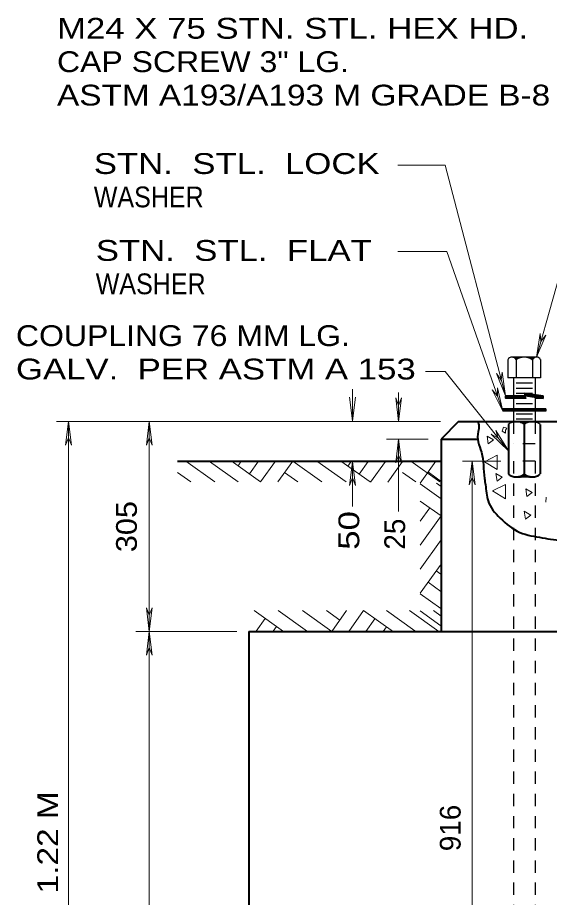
# Model space of a CAD drawing. Extents: x 312583 to 312854, y 144419 to 144597.
# Drawn here: x 312623.61 to 312643.06, y 144483.85 to 144515.99 of the extents above; entities that cross this region are included whole.
import ezdxf

# ---------------------------------------------------------------- set-up
doc = ezdxf.new("R2010")
doc.units = 0
doc.header["$LTSCALE"] = 0.3
doc.linetypes.add('SHORT_DASHED', pattern=[2.7, 1.5, -1.2])
for name, color, linetype, lineweight in [('1', 7, 'Continuous', 25), ('2', 7, 'Continuous', 13), ('52', 7, 'Continuous', 13)]:
    doc.layers.add(name, color=color, linetype=linetype, lineweight=lineweight)

msp = doc.modelspace()

# ---------------------------------------------------------------- linework, layer by layer
at = {"layer": '1'}
for p, q in [((312641.5397, 144503.4947), (312641.5397, 144502.8277)), ((312642.59, 144503.5867), (312641.693, 144503.5867)), ((312641.8387, 144503.4947), (312641.8387, 144502.8277)), ((312642.4367, 144503.4947), (312642.4367, 144502.8277)), ((312642.7357, 144503.4947), (312642.7357, 144502.8277)), ((312642.7357, 144502.8277), (312641.5397, 144502.8277)), ((312641.739, 144502.8277), (312641.739, 144501.233)), ((312641.8387, 144502.6437), (312642.4367, 144502.6437)), ((312642.5363, 144502.8277), (312642.5363, 144501.233)), ((312641.8387, 144502.452), (312642.4367, 144502.452)), ((312642.1683, 144502.176), (312641.4477, 144502.176)), ((312641.4477, 144502.1683), (312641.4477, 144502.0763)), ((312642.199, 144502.0763), (312641.4477, 144502.0763)), ((312641.8387, 144502.268), (312642.4367, 144502.268)), ((312642.8277, 144502.176), (312642.8277, 144502.0763)), ((312642.9273, 144501.7007), (312641.348, 144501.7007)), ((312641.348, 144501.7007), (312641.348, 144501.6087)), ((312642.9273, 144501.6777), (312641.348, 144501.6777)), ((312641.8387, 144501.8923), (312642.4367, 144501.8923)), ((312642.9273, 144501.7007), (312642.9273, 144501.6087)), ((312642.9273, 144501.6547), (312641.348, 144501.6547)), ((312642.9273, 144501.624), (312641.348, 144501.624)), ((312642.9273, 144501.6087), (312641.348, 144501.6087)), ((312641.8387, 144501.509), (312642.4367, 144501.509)), ((312642.5363, 144501.233), (312641.739, 144501.233)), ((312641.8387, 144501.325), (312642.4367, 144501.325)), ((312642.429, 144501.233), (312641.8463, 144501.233))]:
    msp.add_line(p, q, dxfattribs=at)
at = {"layer": '1', "lineweight": 40}
for p, q in [((312639.738, 144501.233), (312639.094, 144500.589)), ((312639.738, 144501.233), (312651.238, 144501.233)), ((312641.555, 144501.1257), (312641.555, 144499.3163)), ((312642.1377, 144501.233), (312642.1377, 144499.209)), ((312642.7203, 144501.1257), (312642.7203, 144499.3163)), ((312639.094, 144500.589), (312639.094, 144493.5663)), ((312639.094, 144500.589), (312640.428, 144500.589)), ((312629.4647, 144499.784), (312639.094, 144499.784)), ((312632.0713, 144493.5663), (312632.0713, 144470.5663)), ((312632.0713, 144493.5663), (312658.9047, 144493.5663))]:
    msp.add_line(p, q, dxfattribs=at)
at = {"layer": '1', "linetype": 'SHORT_DASHED'}
for p, q in [((312641.739, 144501.233), (312641.739, 144500.4203)), ((312642.5363, 144501.233), (312642.5363, 144500.4203)), ((312642.5363, 144500.4203), (312641.739, 144500.4203)), ((312642.5363, 144499.784), (312641.739, 144499.784)), ((312641.739, 144499.784), (312641.739, 144477.6273)), ((312642.5363, 144499.784), (312642.5363, 144477.6273)), ((312642.429, 144499.209), (312641.8463, 144499.209))]:
    msp.add_line(p, q, dxfattribs=at)
at = {"layer": '1'}
for points in [[(312641.7237, 144503.5867), (312642.061, 144503.579), (312642.0073, 144503.5713), (312641.969, 144503.5637), (312641.9077, 144503.5407), (312641.8387, 144503.4947), (312641.8157, 144503.533), (312641.7927, 144503.556), (312641.739, 144503.579), (312642.038, 144503.579), (312641.9537, 144503.5637), (312641.8923, 144503.533), (312641.8463, 144503.5023), (312641.7927, 144503.5483), (312641.762, 144503.5713), (312641.9997, 144503.579), (312641.9153, 144503.5483), (312641.8463, 144503.51), (312641.7773, 144503.5713), (312641.969, 144503.5713), (312641.8387, 144503.5177), (312641.7927, 144503.5637), (312641.9537, 144503.5713), (312641.8387, 144503.5253), (312641.8003, 144503.5637), (312641.923, 144503.5637), (312641.8387, 144503.5407), (312641.8157, 144503.556), (312641.8923, 144503.5637), (312641.8463, 144503.5407), (312641.831, 144503.556), (312641.8693, 144503.556), (312641.8463, 144503.5483)], [(312642.5517, 144503.5867), (312642.2143, 144503.579), (312642.268, 144503.5713), (312642.3063, 144503.5637), (312642.3753, 144503.5407), (312642.4367, 144503.4947), (312642.4597, 144503.533), (312642.4827, 144503.556), (312642.5363, 144503.579), (312642.245, 144503.579), (312642.3217, 144503.5637), (312642.383, 144503.533), (312642.429, 144503.5023), (312642.4827, 144503.5483), (312642.5133, 144503.5713), (312642.2757, 144503.579), (312642.36, 144503.5483), (312642.429, 144503.51), (312642.498, 144503.5713), (312642.3063, 144503.5713), (312642.4367, 144503.5177), (312642.4903, 144503.5637), (312642.3293, 144503.5713), (312642.4367, 144503.5253), (312642.475, 144503.5637), (312642.3523, 144503.5637), (312642.4367, 144503.5407), (312642.4597, 144503.556), (312642.383, 144503.5637), (312642.429, 144503.5407), (312642.4443, 144503.556), (312642.4137, 144503.556), (312642.429, 144503.5483)], [(312642.1837, 144502.0917), (312641.4553, 144502.0917), (312641.4553, 144502.1607), (312642.153, 144502.1607), (312642.176, 144502.0993), (312641.4707, 144502.0993), (312641.4707, 144502.1453), (312642.1453, 144502.1453), (312642.1607, 144502.107), (312641.486, 144502.1147), (312641.4937, 144502.13), (312641.4937, 144502.1377), (312642.1453, 144502.1377), (312642.153, 144502.1223), (312641.5013, 144502.1223)], [(312642.8277, 144502.176), (312642.1377, 144502.268), (312642.199, 144502.0763)], [(312642.5363, 144502.0763), (312642.8277, 144502.0917), (312642.82, 144502.1607), (312642.153, 144502.2527), (312642.1837, 144502.1837), (312642.544, 144502.13), (312642.5517, 144502.0917), (312642.8123, 144502.0993), (312642.8123, 144502.153), (312642.1683, 144502.2373), (312642.1913, 144502.1913), (312642.5593, 144502.13), (312642.567, 144502.0993), (312642.8047, 144502.107), (312642.8047, 144502.1377), (312642.199, 144502.222), (312642.199, 144502.2067), (312642.5517, 144502.1377), (312642.5747, 144502.13), (312642.6513, 144502.1147), (312642.7893, 144502.1223), (312642.2143, 144502.2143), (312642.6973, 144502.1223)], [(312642.1683, 144502.176), (312642.8277, 144502.0763), (312642.5363, 144502.0763)], [(312642.3523, 144501.2253), (312641.923, 144501.2253), (312641.969, 144501.2177), (312642.015, 144501.2023), (312642.061, 144501.1793), (312642.0917, 144501.164), (312642.13, 144501.141), (312642.1377, 144501.1333), (312642.222, 144501.187), (312642.291, 144501.21), (312642.3293, 144501.2253), (312641.9537, 144501.2253), (312641.9843, 144501.2177), (312642.015, 144501.21), (312642.061, 144501.1947), (312642.107, 144501.1717), (312642.1223, 144501.1563), (312642.1377, 144501.141), (312642.2143, 144501.187), (312642.291, 144501.2177), (312642.0073, 144501.2177), (312642.0763, 144501.1947), (312642.1377, 144501.1563), (312642.2603, 144501.21), (312642.038, 144501.2177), (312642.1377, 144501.1487), (312642.2373, 144501.21), (312642.0533, 144501.21), (312642.13, 144501.1717), (312642.199, 144501.2023), (312642.084, 144501.2023), (312642.1377, 144501.187), (312642.199, 144501.1947), (312642.1607, 144501.1717), (312642.153, 144501.2023), (312642.1453, 144501.164), (312642.1147, 144501.1947), (312642.0993, 144501.1947), (312642.0763, 144501.2023)]]:
    msp.add_lwpolyline(points, dxfattribs=at)
at = {"layer": '1', "lineweight": 40}
msp.add_lwpolyline([(312642.3523, 144499.209), (312641.923, 144499.209), (312641.969, 144499.2167), (312642.015, 144499.232), (312642.061, 144499.255), (312642.0917, 144499.2703), (312642.13, 144499.301), (312642.1377, 144499.301), (312642.222, 144499.255), (312642.291, 144499.2243), (312642.3293, 144499.2167), (312641.9537, 144499.209), (312641.9843, 144499.2167), (312642.015, 144499.2243), (312642.061, 144499.2397), (312642.107, 144499.2627), (312642.1223, 144499.278), (312642.1377, 144499.2933), (312642.2143, 144499.2473), (312642.291, 144499.2167), (312642.0073, 144499.2167), (312642.0763, 144499.2397), (312642.1377, 144499.278), (312642.2603, 144499.2243), (312642.038, 144499.2167), (312642.1377, 144499.2857), (312642.2373, 144499.2243), (312642.0533, 144499.2243), (312642.13, 144499.2703), (312642.199, 144499.232), (312642.084, 144499.232), (312642.1377, 144499.2473), (312642.199, 144499.2397), (312642.1607, 144499.2627), (312642.153, 144499.2397), (312642.1453, 144499.278), (312642.1147, 144499.2473), (312642.0993, 144499.2397), (312642.0763, 144499.2397)], dxfattribs=at)
at = {"layer": '1'}
for centre, radius, start, end in [((312641.6887, 144503.4197), 0.1659, 25.60064, 154.39936), ((312642.1377, 144503.0632), 0.5224, 55.04559, 124.95441), ((312642.5866, 144503.4197), 0.1659, 25.60064, 154.39936), ((312641.8456, 144500.7751), 0.4545, 50.00693, 129.99306), ((312642.4298, 144500.7751), 0.4545, 50.00694, 129.99307)]:
    msp.add_arc(centre, radius, start, end, dxfattribs=at)
at = {"layer": '1', "lineweight": 40}
for centre, start, end in [((312641.8456, 144499.6613), 230.00694, 309.99307), ((312642.4298, 144499.6613), 230.00693, 309.99306)]:
    msp.add_arc(centre, 0.4545, start, end, dxfattribs=at)
msp.add_spline([(312640.4433, 144501.2407), (312640.4817, 144501.0643), (312640.451, 144500.865), (312640.451, 144500.4893), (312640.5737, 144500.1137), (312640.681, 144499.1477), (312640.7193, 144498.9177), (312640.8113, 144498.335), (312641.256, 144497.7063), (312641.9767, 144497.185), (312642.797, 144496.9857), (312643.6097, 144496.9167), (312644.2383, 144496.9857), (312644.637, 144496.7863), (312645.465, 144496.679), (312646.3927, 144496.6943), (312646.7147, 144496.7863), (312647.3587, 144497.185), (312647.9797, 144497.4763), (312648.524, 144497.6143), (312649.1833, 144497.6527), (312649.8963, 144497.7753), (312650.3103, 144498.036), (312650.341, 144498.7873), (312650.3563, 144499.6383), (312650.5633, 144500.1673), (312650.456, 144500.3437), (312650.502, 144500.7193), (312650.7243, 144500.9263), (312650.916, 144501.233)], degree=3, dxfattribs=at)
at = {"layer": '2'}
for p, q in [((312645.9633, 144515.654), (312642.59, 144503.5867)), ((312637.5147, 144510.594), (312639.2397, 144510.594)), ((312639.2397, 144510.594), (312641.4477, 144502.1683)), ((312637.5147, 144507.443), (312639.301, 144507.443)), ((312639.301, 144507.443), (312641.348, 144501.6087)), ((312642.59, 144503.5867), (312642.7203, 144504.4453)), ((312642.59, 144503.5867), (312642.9197, 144504.3917)), ((312642.7203, 144504.4453), (312642.7433, 144504.154)), ((312642.9197, 144504.3917), (312642.7433, 144504.154)), ((312638.5267, 144503.0653), (312639.2397, 144503.0653)), ((312639.2397, 144503.0653), (312641.555, 144500.1597)), ((312641.1257, 144502.981), (312641.2943, 144502.7433)), ((312641.4477, 144502.1683), (312641.1257, 144502.981)), ((312641.3327, 144503.0347), (312641.2943, 144502.7433)), ((312641.4477, 144502.1683), (312641.3327, 144503.0347)), ((312640.9647, 144502.3907), (312641.1563, 144502.1607)), ((312641.348, 144501.6087), (312640.9647, 144502.3907)), ((312641.164, 144502.4597), (312641.1563, 144502.1607)), ((312641.348, 144501.6087), (312641.164, 144502.4597)), ((312637.438, 144502.0993), (312637.5453, 144501.8233)), ((312637.5453, 144501.233), (312637.438, 144502.0993)), ((312637.5453, 144501.233), (312637.5453, 144502.291)), ((312637.6527, 144502.0993), (312637.5453, 144501.8233)), ((312637.5453, 144501.233), (312637.6527, 144502.0993)), ((312639.071, 144501.233), (312625.0333, 144501.233)), ((312625.478, 144501.233), (312625.3707, 144500.3667)), ((312625.478, 144470.5663), (312625.478, 144501.233)), ((312625.478, 144501.233), (312625.5853, 144500.3667)), ((312628.4297, 144501.233), (312628.3223, 144500.3667)), ((312628.4297, 144501.233), (312628.537, 144500.3667)), ((312640.9263, 144500.7653), (312641.187, 144500.6197)), ((312641.555, 144500.1597), (312640.9263, 144500.7653)), ((312641.095, 144500.9033), (312641.187, 144500.6197)), ((312641.555, 144500.1597), (312641.095, 144500.9033)), ((312625.3707, 144500.3667), (312625.478, 144500.6427)), ((312625.5853, 144500.3667), (312625.478, 144500.6427)), ((312628.3223, 144500.3667), (312628.4297, 144500.6427)), ((312628.537, 144500.3667), (312628.4297, 144500.6427)), ((312638.6263, 144500.589), (312637.1007, 144500.589)), ((312637.5453, 144500.589), (312637.438, 144499.7227)), ((312637.5453, 144497.9407), (312637.5453, 144500.589)), ((312637.5453, 144500.589), (312637.6527, 144499.7227)), ((312630.8293, 144499.025), (312629.7637, 144499.784)), ((312631.6727, 144499.025), (312630.63, 144499.7687)), ((312632.5007, 144499.025), (312631.4197, 144499.7993)), ((312631.7877, 144499.784), (312631.6727, 144499.6153)), ((312632.4163, 144499.784), (312632.0867, 144499.324)), ((312633.045, 144499.784), (312632.5007, 144499.025)), ((312633.6737, 144499.784), (312633.1293, 144499.025)), ((312634.7393, 144499.025), (312633.6737, 144499.784)), ((312635.621, 144499.025), (312634.5553, 144499.784)), ((312636.5027, 144499.025), (312635.437, 144499.784)), ((312635.805, 144499.7763), (312635.69, 144499.6077)), ((312636.4337, 144499.7763), (312636.104, 144499.3087)), ((312637.0623, 144499.7763), (312636.518, 144499.0173)), ((312637.691, 144499.7763), (312637.1467, 144499.0173)), ((312637.438, 144499.7227), (312637.5453, 144499.9987)), ((312637.6527, 144499.7227), (312637.5453, 144499.9987)), ((312639.0557, 144499.025), (312637.99, 144499.784)), ((312638.335, 144498.9867), (312638.91, 144499.784)), ((312641.279, 144499.784), (312639.876, 144499.784)), ((312640.2287, 144499.784), (312640.1213, 144498.9177)), ((312640.2287, 144499.784), (312640.2287, 144476.7457)), ((312640.2287, 144499.784), (312640.336, 144498.9177)), ((312629.9477, 144499.025), (312629.4647, 144499.37)), ((312633.8653, 144499.025), (312633.3747, 144499.37)), ((312638.174, 144499.025), (312637.691, 144499.37)), ((312639.094, 144499.0403), (312638.634, 144499.3777)), ((312640.1213, 144498.9177), (312640.2287, 144499.1937)), ((312640.336, 144498.9177), (312640.2287, 144499.1937)), ((312639.094, 144498.4117), (312638.335, 144498.956)), ((312639.094, 144498.864), (312638.9253, 144498.9867)), ((312642.9197, 144498.2813), (312642.9427, 144498.4653)), ((312639.094, 144497.7907), (312638.335, 144498.3273)), ((312638.335, 144497.599), (312638.68, 144498.082)), ((312638.335, 144496.7173), (312639.094, 144497.7907)), ((312638.335, 144495.8357), (312639.094, 144496.909)), ((312638.335, 144494.9617), (312639.094, 144496.0273)), ((312639.0863, 144495.6517), (312638.9177, 144495.7743)), ((312639.0863, 144495.023), (312638.6187, 144495.3603)), ((312639.0863, 144494.402), (312638.3273, 144494.9387)), ((312628.3223, 144494.4327), (312628.4297, 144494.1567)), ((312628.4297, 144493.5663), (312628.3223, 144494.4327)), ((312628.537, 144494.4327), (312628.4297, 144494.1567)), ((312628.4297, 144493.5663), (312628.537, 144494.4327)), ((312632.263, 144494.3253), (312633.3363, 144493.5663)), ((312633.1447, 144494.3253), (312634.218, 144493.5663)), ((312634.0263, 144494.3253), (312635.0997, 144493.5663)), ((312634.908, 144494.3253), (312635.391, 144493.9803)), ((312635.0997, 144493.5663), (312635.6363, 144494.3253)), ((312635.7207, 144493.5663), (312636.265, 144494.3253)), ((312636.265, 144494.3253), (312637.3537, 144493.551)), ((312637.1007, 144494.3253), (312638.1357, 144493.5817)), ((312637.944, 144494.3253), (312639.0097, 144493.5663)), ((312639.0863, 144493.7733), (312638.3273, 144494.3177)), ((312638.818, 144494.3253), (312639.094, 144494.126)), ((312632.332, 144493.574), (312632.6693, 144494.0417)), ((312636.3493, 144493.5663), (312636.679, 144494.0263)), ((312632.9607, 144493.574), (312633.0833, 144493.7427)), ((312636.978, 144493.5663), (312637.1007, 144493.735)), ((312631.6343, 144493.5663), (312627.939, 144493.5663)), ((312628.4297, 144493.5663), (312628.3223, 144492.7)), ((312628.4297, 144493.5663), (312628.537, 144492.7)), ((312628.3223, 144492.7), (312628.4297, 144492.976)), ((312628.537, 144492.7), (312628.4297, 144492.976))]:
    msp.add_line(p, q, dxfattribs=at)
msp.add_lwpolyline([(312628.4297, 144470.5663), (312628.4297, 144493.5663), (312628.4297, 144501.233)], dxfattribs=at)
for points in [[(312641.4477, 144500.911), (312641.5013, 144500.9953), (312641.3787, 144501.026), (312641.325, 144500.8803), (312641.4477, 144500.8037)], [(312640.819, 144500.4127), (312641.0107, 144500.5583), (312640.7807, 144500.704)], [(312641.1487, 144499.4773), (312641.1487, 144499.9987), (312640.6887, 144499.761)], [(312641.141, 144499.0557), (312641.3327, 144499.2013), (312641.1027, 144499.3393)], [(312641.4477, 144498.4117), (312641.4477, 144498.933), (312640.98, 144498.6953)], [(312642.2297, 144498.496), (312642.429, 144498.6417), (312642.1913, 144498.7797)], [(312642.176, 144497.668), (312642.3753, 144497.8137), (312642.1377, 144497.9593)]]:
    msp.add_lwpolyline(points, close=True, dxfattribs=at)
at = {"layer": '52'}
for p, q in [((312635.7513, 144502.1223), (312635.8587, 144501.256)), ((312635.7513, 144498.8947), (312635.8587, 144499.761)), ((312635.8587, 144499.1707), (312635.7513, 144498.8947)), ((312635.966, 144498.8947), (312635.8587, 144499.1707))]:
    msp.add_line(p, q, dxfattribs=at)
for points in [[(312635.8587, 144502.4137), (312635.8587, 144501.256), (312635.966, 144502.1223)], [(312635.8587, 144498.1276), (312635.8587, 144499.761), (312635.966, 144498.8947)]]:
    msp.add_lwpolyline(points, dxfattribs=at)

# ---------------------------------------------------------------- texts
at = {"layer": '2'}
for s, width, p in [('M24 X 75 STN. STL. HEX HD.', 1.25, (312625.0561, 144515.2154)), ('CAP SCREW 3" LG.', 1.15, (312625.0561, 144513.9954)), ('ASTM A193/A193 M GRADE B-8', 1.2, (312625.0561, 144512.7754)), ('STN.  STL.  LOCK', 1.25, (312626.4016, 144510.2758)), ('WASHER', 0.9, (312626.4016, 144509.0558)), ('STN.  STL.  FLAT', 1.25, (312626.4731, 144507.1018)), ('WASHER', 0.9, (312626.4731, 144505.8818)), ('COUPLING 76 MM LG.', 1.15, (312623.5552, 144503.9891)), ('GALV.  PER ASTM A 153', 1.25, (312623.5552, 144502.7691))]:
    msp.add_text(s, height=0.76, dxfattribs=dict(at, width=width)).set_placement(p)
for s, width, p in [('305', 1.1, (312627.9754, 144496.462)), ('50 ', 1.25, (312636.1052, 144496.5489)), ('1.22 M', 1.2, (312625.0955, 144483.9976))]:
    msp.add_text(s, height=0.76, rotation=90, dxfattribs=dict(at, width=width)).set_placement(p)
for s, p in [('25', (312637.7819, 144496.5544)), ('916', (312639.8104, 144485.5382))]:
    msp.add_text(s, height=0.76, rotation=90, dxfattribs=at).set_placement(p)

doc.saveas('drawing.dxf')
